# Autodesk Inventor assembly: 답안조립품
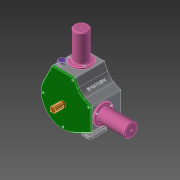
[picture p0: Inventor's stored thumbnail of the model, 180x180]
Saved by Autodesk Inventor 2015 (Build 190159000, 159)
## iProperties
Created: 2022-01
Part Number: 답안조립품
Document SubType Name: Assembly
Designer: user
Mass: 3748.67 g
Surface Area: 4101.78 cm^2
Volume: 1119.43 cm^3
Density: 3.34872 g/cm^3
Author: user
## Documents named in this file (13)
- C:\Users\user\Desktop\620117V1003\답안조립품.iam
- C:\Users\user\Desktop\620117V1003\너트 M3.ipt
- C:\Users\user\Desktop\620117V1003\베어링 20 x 37 x 9.ipt
- C:\Users\user\Desktop\620117V1003\본체.ipt
- C:\Users\user\Desktop\620117V1003\볼트 M3 x 12.ipt
- C:\Users\user\Desktop\620117V1003\실린더.ipt
- C:\Users\user\Desktop\620117V1003\앞커버.ipt
- C:\Users\user\Desktop\620117V1003\축.ipt
- C:\Users\user\Desktop\620117V1003\측정게이지.ipt
- C:\Users\user\Desktop\620117V1003\커넥팅로드 캡.ipt
- C:\Users\user\Desktop\620117V1003\커넥팅로드.ipt
- C:\Users\user\Desktop\620117V1003\피스톤 핀.ipt
- C:\Users\user\Desktop\620117V1003\피스톤.ipt
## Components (4 placed, 2 different names)
1. 피스톤 핀:1
2. 피스톤:1
3. 피스톤 핀:2
4. 피스톤:2
